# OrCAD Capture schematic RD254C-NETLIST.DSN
size A3
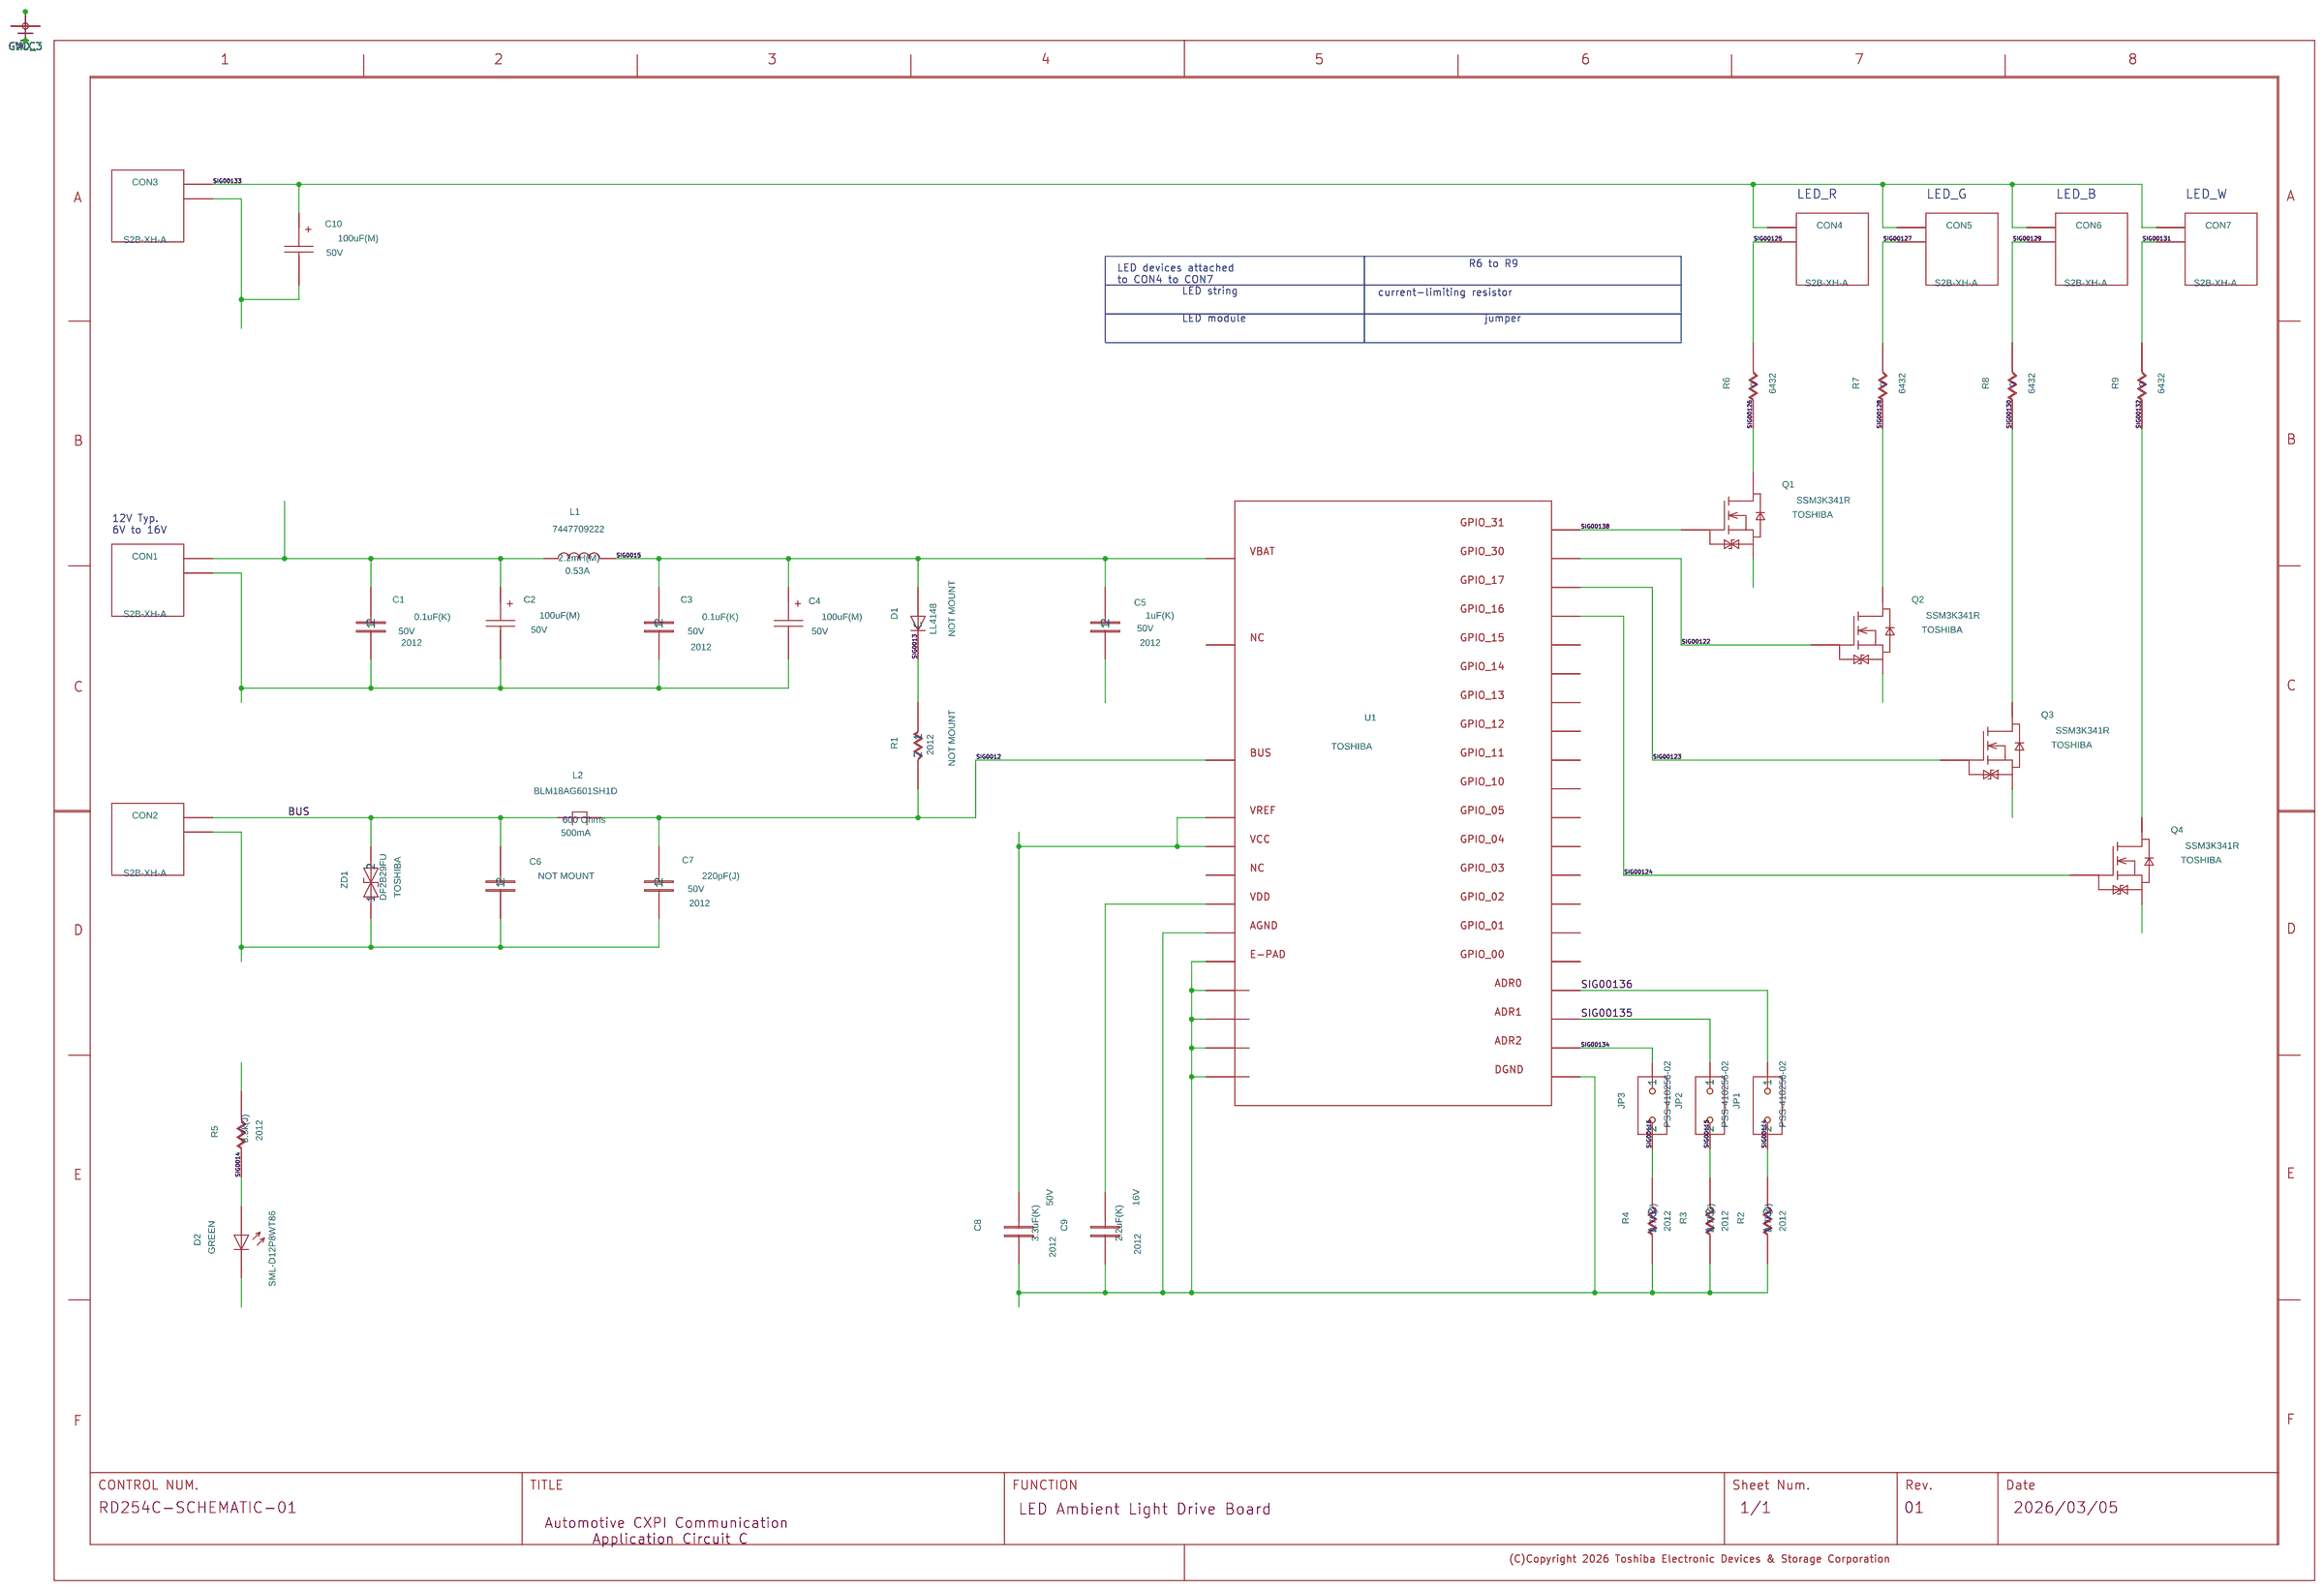
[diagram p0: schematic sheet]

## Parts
C1  C
C2  CP
C3  C
C4  CP
C5  C
C6  C
C7  C
C8  C
C9  C
C10  CP
CON1  S2B-XH-A
CON2  S2B-XH-A
CON3  S2B-XH-A
CON4  S2B-XH-A
CON5  S2B-XH-A
CON6  S2B-XH-A
CON7  S2B-XH-A
D1  D
D2  LED
JP1  PSS-410256-02
JP2  PSS-410256-02
JP3  PSS-410256-02
L1  L
L2  FB
Q1  SSM3K341R
Q2  SSM3K341R
Q3  SSM3K341R
Q4  SSM3K341R
R1  R
R2  R
R3  R
R4  R
R5  R
R6  R
R7  R
R8  R
R9  R
U1  TB9033FTGIC_VERB
U?#1  WAKU_DEF100
ZD1  ZDB

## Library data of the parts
C1 C3 = C: COMPONENTTYPE: 4; SAVECOUNT: 0; SIZECODESMD: 2012; VAL1: 0.1uF(K); VAL2: 50V
C2 C4 C10 = CP: COMP: C; COMPONENTTYPE: 4; VAL1: 100uF(M); VAL2: 50V
C5 = C: COMPONENTTYPE: 4; NOTMOUNT: MOUNT; SAVECOUNT: 0; SIZECODESMD: 2012; VAL1: 1uF(K); VAL2: 50V
C6 = C: COMPONENTTYPE: 4; NOTMOUNT: NOT MOUNT; SAVECOUNT: 0
C7 = C: COMPONENTTYPE: 4; SAVECOUNT: 0; SIZECODESMD: 2012; VAL1: 220pF(J); VAL2: 50V
C8 = C#1: COMPONENTTYPE: 4; CaptureCellPackProp: C##1; SAVECOUNT: 0; SIZECODESMD: 2012; VAL1: 3.3uF(K); VAL2: 50V
C9 = C#1: COMPONENTTYPE: 4; CaptureCellPackProp: C##1; SAVECOUNT: 0; SIZECODESMD: 2012; VAL1: 2.2uF(K); VAL2: 16V
CON1-CON7 = S2B-XH-A: COMPONENTTYPE: 4
D1 = D: COMP: LL4148; COMPONENTTYPE: 4; NOTMOUNT: NOT MOUNT; VAL3: LL4148
D2 = LED: COMPONENTTYPE: 4; VAL2: GREEN; VAL3: SML-D12P8WT86
JP1-JP3 = PSS-410256-02: COMPONENTKIND: 135; COMPONENTTYPE: 4
L1 = L: COMP: 7447709222; COMPONENTTYPE: 4; SAVECOUNT: 0; VAL1: 2.2mH(M); VAL2: 0.53A; VAL3: 7447709222
L2 = FB: COMP: BLM18AG601SH1D; COMPONENTTYPE: 4; VAL1: 600 Ohms; VAL2: 500mA; VAL3: BLM18AG601SH1D
Q1-Q4 = SSM3K341R: COMPONENTTYPE: 4; USERCOMPTEXT3: TOSHIBA
R1 = R: COMPONENTTYPE: 4; NOTMOUNT: NOT MOUNT; SAVECOUNT: 0; SIZECODESMD: 2012
R2-R4 = R: COMPONENTTYPE: 4; SAVECOUNT: 0; SIZECODESMD: 2012; VAL1: 4.7k(J); VAL2: 250mW
R5 = R#1: COMPONENTTYPE: 4; CaptureCellPackProp: R##1; SAVECOUNT: 0; SIZECODESMD: 2012; VAL1: 3.3k(J); VAL2: 250mW
R6-R9 = R#2: COMPONENTTYPE: 4; CaptureCellPackProp: R##2; SAVECOUNT: 0; SIZECODESMD: 6432; VAL1: 0; VAL2: 2W
U1 = TB9033FTGIC_VERB: COMPONENTTYPE: 4; USERCOMPTEXT3: TOSHIBA
U?#1 = WAKU_DEF100: COMPONENTTYPE: 2; DATE: 2026/03/05; DRAWINGNUMBER: RD254C-SCHEMATIC-01; FUNCTION: LED Ambient Light Drive Board; REVISION: 01; SHEETNUMBER: 1/1; SHTSAVECOUNT: 56; TITLE: Automotive CXPI Communication / Application Circuit C; UPDATEDATE: 2026.4.23; UPDATETIME: 17:21:36
ZD1 = ZDB: COMP: DF2B29FU; COMPONENTTYPE: 4; USERCOMPTEXT3: TOSHIBA; VAL3: DF2B29FU

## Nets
GND: C1.2(1) C2.1 C3.2(1) C4.1 C5.2(1) C6.2(1) C7.2(1) C8.1 C9.1 C10.1 CON1.1 CON2.1 CON3.1 D2.C Q1.2 Q2.2 Q3.2 Q4.2 R2.2(1) R3.2(1) R4.2(1) U1.1T U1.2T U1.3T U1.4T U1.26 U1.27 U1.E_PAD ZD1.2(1)
VBAT: C1.1(2) C2.2 CON1.2 L1.1 R5.2
BUS: C6.1(2) CON2.2 L2.1 ZD1.1(2)
SIG0012: C7.1(2) L2.2 R1.1(2) U1.28
SIG0013: D1.K(C) R1.2(1)
SIG0014: D2.A R5.1
SIG0015: C3.1(2) C4.2 C5.1(2) D1.A L1.2 U1.1
SIG00114: JP1.1(2) R2.1(2)
SIG00115: JP2.1(2) R3.1(2)
SIG00116: JP3.1(2) R4.1(2)
SIG00122: Q2.1 U1.20
SIG00123: Q3.1 U1.19
SIG00124: Q4.1 U1.18
SIG00125: CON4.1 R6.P_2
SIG00126: Q1.3 R6.P_1
SIG00127: CON5.1 R7.P_2
SIG00128: Q2.3 R7.P_1
SIG00129: CON6.1 R8.P_2
SIG00130: Q3.3 R8.P_1
SIG00131: CON7.1 R9.P_2
SIG00132: Q4.3 R9.P_1
SIG00133: C10.2 CON3.2 CON4.2 CON5.2 CON6.2 CON7.2
SIG00134: JP3.2(1) U1.5
SIG00135: JP2.2(1) U1.4
SIG00136: JP1.2(1) U1.3
SIG00138: Q1.1 U1.21
VP_1R5_C: C9.2 U1.22
VP_5R0_C: C8.2 U1.24 U1.25

Not connected (* = marked no-connect by the designer): U1 2 6 7 8 9 10 11 12 13 14 15 16 17 23

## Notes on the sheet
- LED_R
- LED_G
- LED_B
- LED_W
- R6 to R9
- LED devices attached
  to CON4 to CON7
- LED string
- current-limiting resistor
- LED module
- jumper
- 12V Typ.
  6V to 16V
